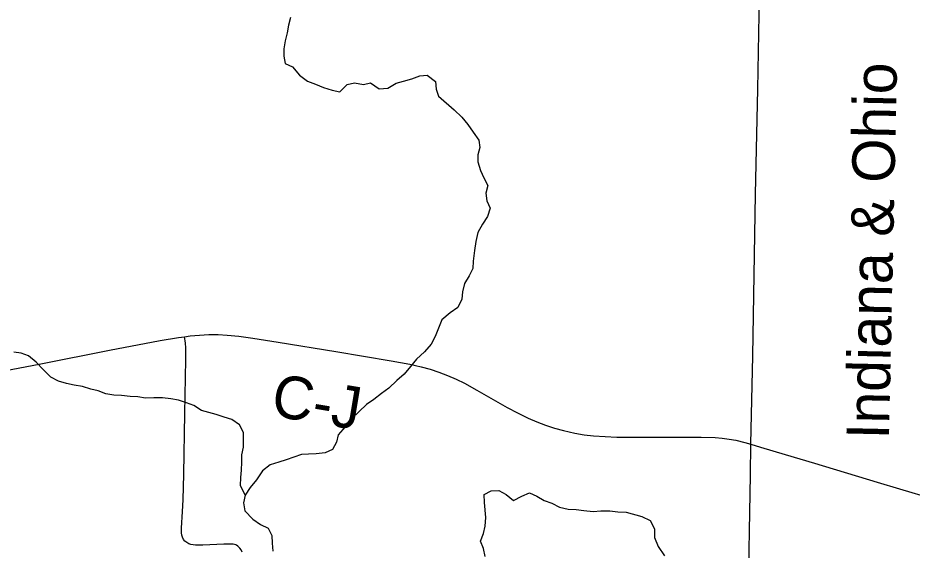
# Model space of a CAD drawing. Extents: x -21.7 to 34, y 0 to 22.
# Drawn here: x 24.718 to 25.906, y 19.527 to 20.235 of the extents above; entities that cross this region are included whole.
import ezdxf

# ---------------------------------------------------------------- set-up
doc = ezdxf.new("R2010")
doc.units = 0
for name, color, linetype in [('GM_X_County_Road', 7, 'Continuous'), ('GM_X_County_Road_Text', 7, 'Continuous'), ('GM_X_Minor_River', 7, 'Continuous'), ('GM_X_Rail_Line_Text', 7, 'Continuous'), ('GM_X_State_Route', 7, 'Continuous'), ('GM_X_Township_Road', 7, 'Continuous')]:
    doc.layers.add(name, color=color, linetype=linetype)

msp = doc.modelspace()

# ---------------------------------------------------------------- linework, layer by layer
at = {"layer": 'GM_X_County_Road'}
for points in [[(24.69, 19.7638), (24.7481, 19.775), (24.8396, 19.793), (24.9068, 19.8058), (24.9313, 19.8101), (24.9391, 19.8111)], [(24.9391, 19.8111), (24.9466, 19.8122), (24.959, 19.8133), (24.9714, 19.8138), (24.9838, 19.8138), (24.9961, 19.8131), (25.0116, 19.8116), (25.03, 19.8092), (25.0638, 19.8038), (25.1406, 19.7915), (25.2142, 19.7791), (25.2386, 19.7746), (25.2537, 19.7712), (25.2657, 19.7679), (25.2774, 19.7641), (25.289, 19.7596), (25.3003, 19.7546), (25.3114, 19.7491), (25.3278, 19.7402), (25.3683, 19.717), (25.382, 19.7097), (25.3961, 19.7028), (25.4075, 19.6979), (25.4192, 19.6934), (25.431, 19.6896), (25.4431, 19.6862), (25.4583, 19.6828), (25.4706, 19.6806), (25.483, 19.6792), (25.4985, 19.6782), (25.5141, 19.6777), (25.6261, 19.6774), (25.6447, 19.6769), (25.6539, 19.6762), (25.6631, 19.675), (25.6722, 19.6733), (25.6842, 19.6704), (25.6923, 19.668)], [(25.6923, 19.668), (25.7051, 19.6643), (25.7379, 19.6545), (25.7766, 19.6429), (25.8599, 19.6177), (25.8898, 19.609), (25.9344, 19.5956), (26.0507, 19.5613), (26.0678, 19.5561)]]:
    msp.add_lwpolyline(points, dxfattribs=at)
at = {"layer": 'GM_X_Minor_River'}
for points in [[(25.08, 20.2354), (25.0775, 20.2252), (25.0758, 20.215), (25.0732, 20.2044), (25.0711, 20.1939), (25.0712, 20.184), (25.0729, 20.1745), (25.0827, 20.1697), (25.0923, 20.1588), (25.1027, 20.151), (25.1132, 20.147), (25.1241, 20.1426), (25.1354, 20.1389), (25.1456, 20.1368), (25.1553, 20.1464), (25.1653, 20.1485), (25.177, 20.1463), (25.1865, 20.1488), (25.1981, 20.1405), (25.2095, 20.1414), (25.2206, 20.148), (25.2306, 20.1508), (25.2413, 20.154), (25.252, 20.1579), (25.2619, 20.1589), (25.2727, 20.1506), (25.274, 20.1404), (25.2768, 20.1308), (25.2976, 20.1129), (25.308, 20.1028), (25.3161, 20.0931), (25.3231, 20.0831), (25.3304, 20.0723), (25.3317, 20.0628), (25.3292, 20.053), (25.3293, 20.0435), (25.3329, 20.032), (25.3372, 20.0224), (25.3426, 20.012), (25.3397, 20.0019), (25.341, 19.9916), (25.3457, 19.982), (25.342, 19.9711), (25.3353, 19.9606), (25.3294, 19.9497), (25.3265, 19.9376), (25.3247, 19.9255), (25.3232, 19.9115), (25.3226, 19.9016), (25.3178, 19.8919), (25.3115, 19.8818), (25.3086, 19.8708), (25.308, 19.861), (25.3024, 19.8501), (25.2923, 19.8427), (25.2815, 19.8335), (25.2767, 19.8226), (25.2726, 19.8113), (25.2671, 19.8012), (25.2581, 19.7911), (25.2476, 19.7811), (25.2398, 19.7714), (25.2312, 19.7613), (25.2216, 19.7528), (25.2111, 19.7428), (25.201, 19.7354), (25.191, 19.7277), (25.1813, 19.7211), (25.1713, 19.7114), (25.1616, 19.7025), (25.1529, 19.6913), (25.1436, 19.6805), (25.1411, 19.6707), (25.1359, 19.661), (25.1263, 19.6566), (25.1142, 19.6554), (25.1043, 19.6548), (25.0948, 19.6543), (25.0848, 19.6511), (25.0745, 19.6475), (25.0646, 19.6443), (25.0531, 19.6408), (25.043, 19.6327), (25.0348, 19.6207), (25.0266, 19.6106), (25.0199, 19.6005)], [(25.0199, 19.6005), (25.0138, 19.6132), (25.014, 19.6238), (25.015, 19.6337), (25.0156, 19.6443), (25.0155, 19.6538), (25.0176, 19.6644), (25.0175, 19.6742), (25.0177, 19.6837), (25.0122, 19.6941), (25.0022, 19.7008), (24.992, 19.704), (24.9815, 19.7077), (24.9717, 19.7102), (24.9619, 19.7131), (24.9518, 19.7197), (24.942, 19.723), (24.9314, 19.7266), (24.9209, 19.7284), (24.9099, 19.7298), (24.8985, 19.7297), (24.8875, 19.7295), (24.8773, 19.7309), (24.8671, 19.7315), (24.8553, 19.7329), (24.8455, 19.7335), (24.8349, 19.7352), (24.8247, 19.7389), (24.8149, 19.7414), (24.8036, 19.7447), (24.7927, 19.7468), (24.7825, 19.7489), (24.7719, 19.7518), (24.7614, 19.7574), (24.7514, 19.7675), (24.7422, 19.7772), (24.7321, 19.7857), (24.7223, 19.789), (24.7125, 19.7907)], [(25.339, 19.5186), (25.3369, 19.5293), (25.3326, 19.5393), (25.3366, 19.5494), (25.3388, 19.5593), (25.3398, 19.5706), (25.338, 19.5904), (25.3375, 19.6014), (25.3471, 19.6061), (25.357, 19.6067), (25.3667, 19.6012), (25.3764, 19.5933), (25.3879, 19.5992), (25.3979, 19.6035), (25.4076, 19.5991), (25.4174, 19.5932), (25.4275, 19.5899), (25.4376, 19.5844), (25.4493, 19.5819), (25.4599, 19.5812), (25.4702, 19.5802), (25.4823, 19.5788), (25.4925, 19.5797), (25.5047, 19.5795), (25.5153, 19.5781), (25.5263, 19.5779), (25.5474, 19.5721), (25.5583, 19.5669), (25.5641, 19.5554), (25.5642, 19.544), (25.5688, 19.5321), (25.5773, 19.5198)], [(25.0199, 19.6005), (25.0178, 19.59), (25.0194, 19.5797), (25.0302, 19.5684), (25.0402, 19.5614), (25.0507, 19.5566), (25.0554, 19.5466), (25.056, 19.5367), (25.0568, 19.5261)]]:
    msp.add_lwpolyline(points, dxfattribs=at)
at = {"layer": 'GM_X_State_Route'}
msp.add_lwpolyline([(25.6769, 19.0384), (25.6777, 19.0526), (25.6822, 19.1396), (25.6845, 19.2173), (25.6855, 19.2919), (25.6864, 19.3479), (25.6874, 19.3977), (25.6884, 19.453), (25.6916, 19.6272), (25.6923, 19.668), (25.6946, 19.7858), (25.6983, 20.0004), (25.7012, 20.1404), (25.7041, 20.2896)], dxfattribs=at)
at = {"layer": 'GM_X_Township_Road'}
for points in [[(24.69, 19.7638), (24.7481, 19.775), (24.8396, 19.793), (24.9068, 19.8058), (24.9313, 19.8101), (24.9391, 19.8111)], [(25.016, 19.5246), (25.0144, 19.5279), (25.0129, 19.5299), (25.0103, 19.5325), (25.0086, 19.5337), (25.0075, 19.5344), (25.0057, 19.5348), (25.0039, 19.535), (25.0008, 19.5353), (24.9977, 19.5352), (24.9915, 19.5353), (24.9635, 19.534), (24.9541, 19.534), (24.951, 19.5343), (24.9479, 19.5349), (24.945, 19.5358), (24.9423, 19.5373), (24.9399, 19.5393), (24.938, 19.5416), (24.9366, 19.5444), (24.9357, 19.5474), (24.9353, 19.5505), (24.9352, 19.5536), (24.9353, 19.5567), (24.9368, 19.5785), (24.9375, 19.594), (24.9384, 19.6282), (24.9397, 19.7091), (24.9409, 19.7807), (24.941, 19.7963), (24.9406, 19.8025), (24.94, 19.8055), (24.9391, 19.8111)], [(24.9391, 19.8111), (24.9466, 19.8122), (24.959, 19.8133), (24.9714, 19.8138), (24.9838, 19.8138), (24.9961, 19.8131), (25.0116, 19.8116), (25.03, 19.8092), (25.0638, 19.8038), (25.1406, 19.7915), (25.2142, 19.7791), (25.2386, 19.7746), (25.2537, 19.7712), (25.2657, 19.7679), (25.2774, 19.7641), (25.289, 19.7596), (25.3003, 19.7546), (25.3114, 19.7491), (25.3278, 19.7402), (25.3683, 19.717), (25.382, 19.7097), (25.3961, 19.7028), (25.4075, 19.6979), (25.4192, 19.6934), (25.431, 19.6896), (25.4431, 19.6862), (25.4583, 19.6828), (25.4706, 19.6806), (25.483, 19.6792), (25.4985, 19.6782), (25.5141, 19.6777), (25.6261, 19.6774), (25.6447, 19.6769), (25.6539, 19.6762), (25.6631, 19.675), (25.6722, 19.6733), (25.6842, 19.6704), (25.6923, 19.668)], [(25.6923, 19.668), (25.7051, 19.6643), (25.7379, 19.6545), (25.7766, 19.6429), (25.8599, 19.6177), (25.8898, 19.609), (25.9344, 19.5956), (26.0507, 19.5613), (26.0678, 19.5561)]]:
    msp.add_lwpolyline(points, dxfattribs=at)

# ---------------------------------------------------------------- texts
at = {"layer": 'GM_X_County_Road_Text'}
msp.add_text('C-J', height=0.05682, rotation=350.5374, dxfattribs=at).set_placement((25.0525, 19.7063))
at = {"layer": 'GM_X_Rail_Line_Text'}
msp.add_text('Indiana & Ohio', height=0.056629, rotation=88.7669, dxfattribs=at).set_placement((25.8757, 19.6742))

doc.saveas('drawing.dxf')
